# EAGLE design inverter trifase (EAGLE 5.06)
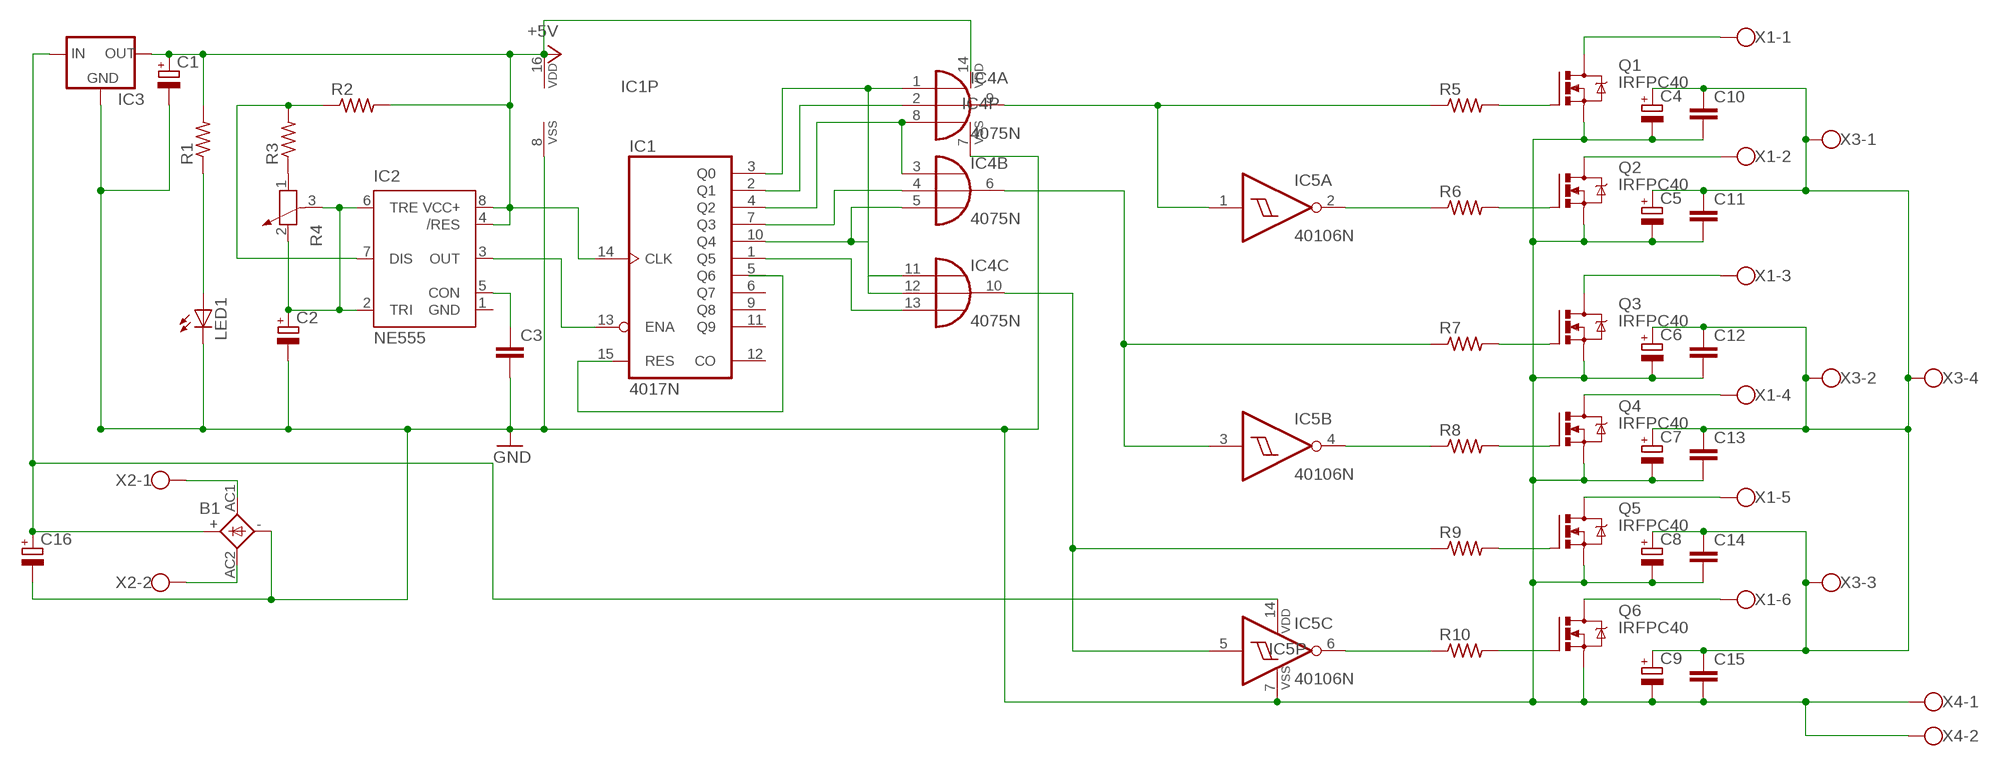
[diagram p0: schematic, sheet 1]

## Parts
B1  1KAB  [1KAB]
C1  CPOL-EUE2.5-7  [E2,5-7]
C2  CPOL-EUE2.5-7  [E2,5-7]
C3  C-EU050-025X075  [C050-025X075]
C4  CPOL-EUE10-25  [EB25D]
C5  CPOL-EUE10-25  [EB25D]
C6  CPOL-EUE10-25  [EB25D]
C7  CPOL-EUE10-25  [EB25D]
C8  CPOL-EUE10-25  [EB25D]
C9  CPOL-EUE10-25  [EB25D]
C10  C-EU050-025X075  [C050-025X075]
C11  C-EU050-025X075  [C050-025X075]
C12  C-EU050-025X075  [C050-025X075]
C13  C-EU050-025X075  [C050-025X075]
C14  C-EU050-025X075  [C050-025X075]
C15  C-EU050-025X075  [C050-025X075]
C16  CPOL-EUE2.5-7  [E2,5-7]
IC1  4017N  [DIL16]
IC2  NE555  [DIL-08]
IC3  78XXS  [78XXS]
IC4  4075N  [DIL14]
IC5  40106N  [DIL14]
LED1  LED3MM  [LED3MM]
Q1  IRFPC40  [TO247BV]
Q2  IRFPC40  [TO247BV]
Q3  IRFPC40  [TO247BV]
Q4  IRFPC40  [TO247BV]
Q5  IRFPC40  [TO247BV]
Q6  IRFPC40  [TO247BV]
R1  R-US_0207/10  [0207/10]
R2  R-US_0207/10  [0207/10]
R3  R-US_0207/10  [0207/10]
R4  POTENTIOMETER_PT-10S  [PT-10S]
R5  R-US_0207/10  [0207/10]
R6  R-US_0207/10  [0207/10]
R7  R-US_0207/10  [0207/10]
R8  R-US_0207/10  [0207/10]
R9  R-US_0207/10  [0207/10]
R10  R-US_0207/10  [0207/10]
X1  W237-6  [W237-6]
X2  W237-102  [W237-102]
X3  W237-4  [W237-4]
X4  W237-102  [W237-102]

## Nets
N$1: IC1.3(Q0) IC4.1(A:I0) IC4.12(C:I1)
N$2: IC1.2(Q1) IC4.2(A:I1)
N$3: IC1.4(Q2) IC4.3(B:I0) IC4.8(A:I2)
N$4: IC1.7(Q3) IC4.4(B:I1)
N$5: IC1.1(Q5) IC4.13(C:I2)
N$7: IC1.10(Q4) IC4.5(B:I2) IC4.11(C:I0)
N$8: IC4.9(A:O) IC5.1(A:I) R5.1
N$9: LED1.A R1.1
N$10: IC4.6(B:O) IC5.3(B:I) R7.1
N$11: IC2.6(TRE) R4.3
N$12: R3.1 R4.1
N$13: IC2.7(DIS) R2.1 R3.2
N$14: IC4.10(C:O) IC5.5(C:I) R9.1
N$15: C2.+ IC2.2(TRI) R4.2
N$16: IC5.2(A:O) R6.1
N$17: IC5.4(B:O) R8.1
N$18: IC5.6(C:O) R10.1
N$19: C3.1 IC2.5(CON)
N$20: Q1.G R5.2
N$21: Q2.G R6.2
N$22: Q3.G R7.2
N$23: Q4.G R8.2
N$24: Q5.G R9.2
N$25: Q6.G R10.2
N$31: Q1.D X1.1
N$32: Q2.D X1.2
N$33: C16.+ IC3.IN IC5.14(P:VDD)
N$34: Q3.D X1.3
N$35: Q4.D X1.4
N$36: Q5.D X1.5
N$37: Q6.D X1.6
N$39: B1.AC1 X2.1
N$40: B1.AC2 X2.2
N$41: IC1.13(ENA) IC2.3(OUT)
N$43: C4.+ C5.+ C6.+ C7.+ C8.+ C9.+ C10.1 C11.1 C12.1 C13.1 C14.1 C15.1 X3.1 X3.2 X3.3 X3.4
VDD: C1.+ IC1.14(CLK) IC1.16(VDD) IC2.4(/RES) IC2.8(VCC+) IC3.OUT R1.2 R2.2 ; supply symbol labelled +5V
VSS: B1.- C1.- C2.- C3.2 C4.- C5.- C6.- C7.- C8.- C9.- C10.2 C11.2 C12.2 C13.2 C14.2 C15.2 C16.- IC1.8(VSS) IC3.GND IC4.7(P:VSS) IC5.7(P:VSS) LED1.K(C) Q1.S Q2.S Q3.S Q4.S Q5.S Q6.S X4.1 X4.2 ; supply symbol labelled GND
Unconnected: B1.+ IC1.5(Q6) IC1.6(Q7) IC1.9(Q8) IC1.11(Q9) IC1.12(CO) IC1.15(RES) IC5.8(D:O) IC5.9(D:I) IC5.10(E:O) IC5.11(E:I) IC5.12(F:O) IC5.13(F:I)

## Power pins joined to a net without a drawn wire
VDD: IC4.14(P:VDD)
VSS: IC2.1(GND)

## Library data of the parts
B1 = rectifier:1KAB: RECTIFIER grid 5,08 x 5,08 mm
C1 C2 C4-C9 C16 = resistor:CPOL-EU: POLARIZED CAPACITOR, European symbol
C3 C10-C15 = resistor:C-EU: CAPACITOR, European symbol
IC1 = 40xx:4017: COUNTER/DIVIDER
IC2 = st-microelectronics:NE555: General purpose bipolar Timer
IC3 = v-reg:78XXS: VOLTAGE REGULATOR
IC4 = 40xx:4075: Triple 3-input OR
IC5 = 40xx:40106: Hex SCHMITT TRIGGER
LED1 = led:LED: LED
Q1-Q6 = transistor-power:IRFPC40: N-CHANNEL MOS FET
R1-R3 R5-R10 = resistor:R-US_: RESISTOR, American symbol
R4 = rcl:POTENTIOMETER_: Potentiometer
X1 = con-wago-500:W237-6: WAGO SCREW CLAMP
X2 X4 = con-wago-500:W237-102: WAGO SCREW CLAMP
X3 = con-wago-500:W237-4: WAGO SCREW CLAMP

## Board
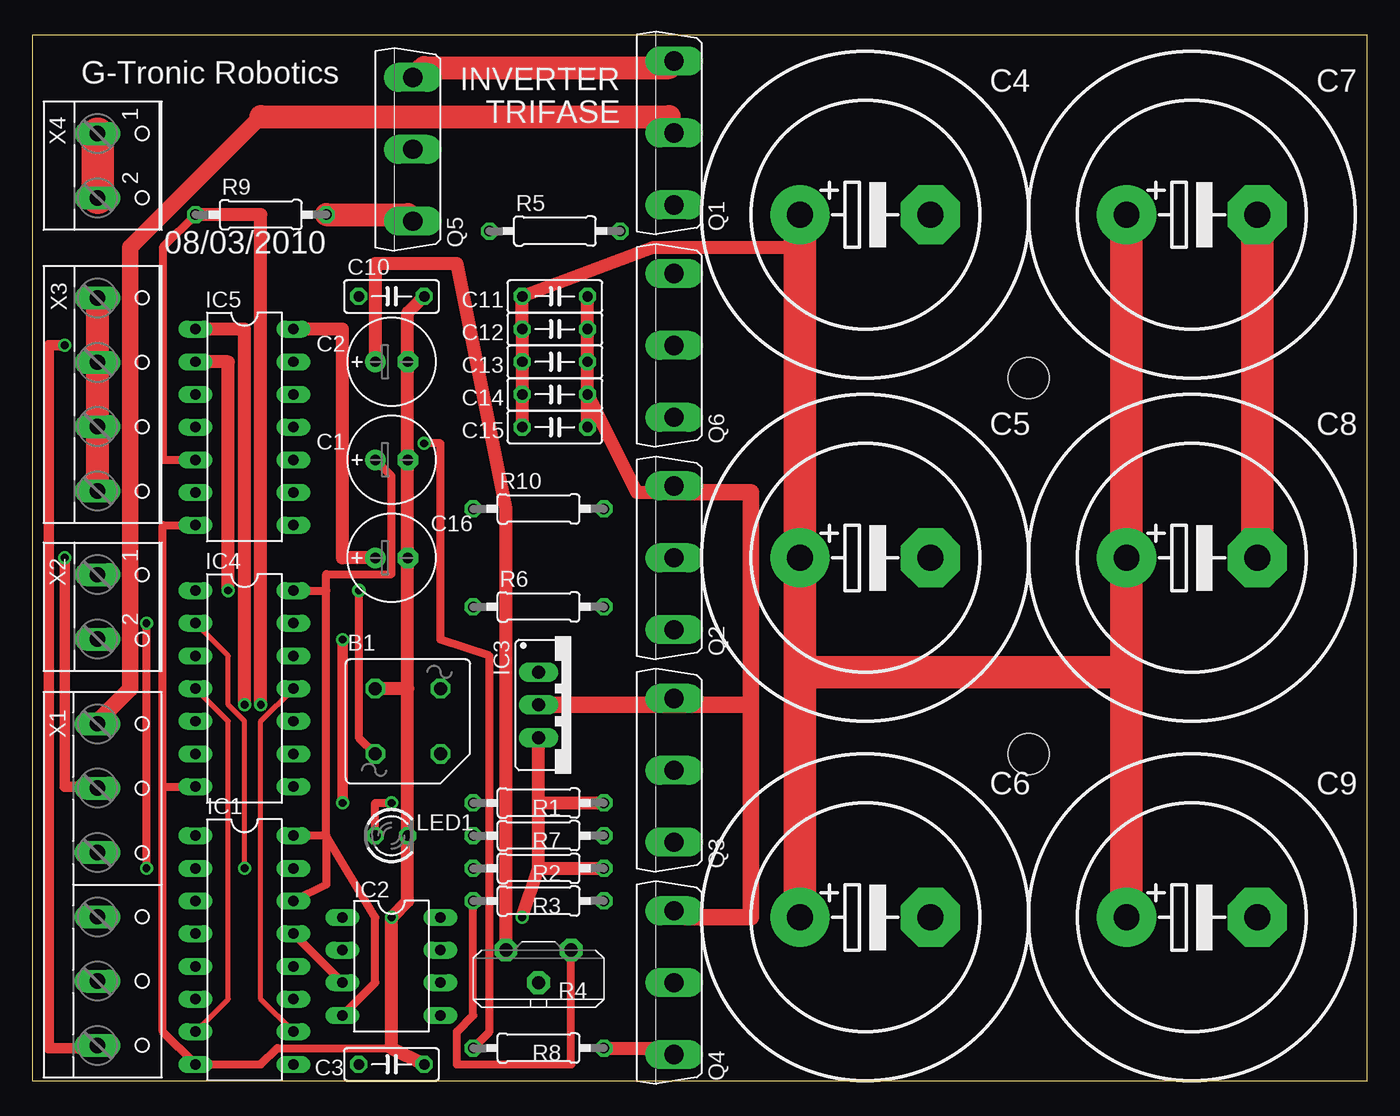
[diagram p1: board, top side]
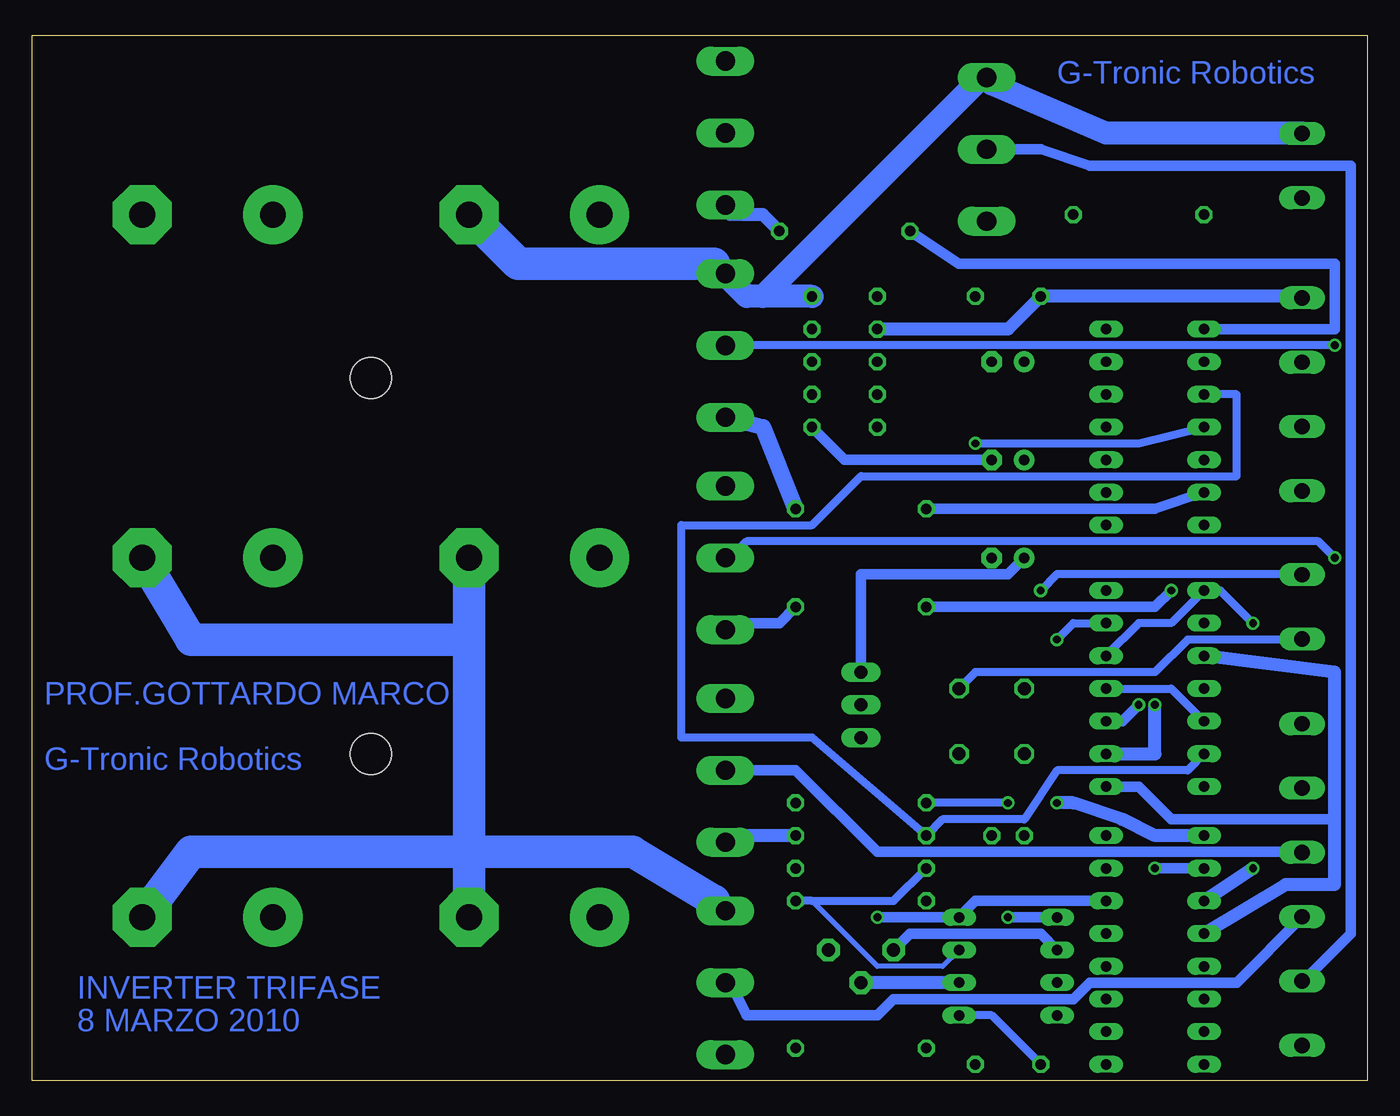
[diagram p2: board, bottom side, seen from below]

Size 103.81 x 81.27 mm. Coordinates in mm from the lower left corner, seen from the top.
Outline: 0,0 103.81,0 103.81,81.27 0,81.27 0,0
Copper layers (1*16): Top 0.035mm / dielectric 1.5mm / Bottom 0.035mm
Design rules "default": minimum track width 10mil, minimum drill 24mil, track to track 8mil, track to pad 8mil, pad to pad 8mil, via to via 8mil, smd to smd 8mil, copper to edge 40mil, drill to drill 8mil, minimum pad ring 10mil, minimum via ring 8mil, stop-mask expansion 4mil, vias tented up to drill 0mil, thermal gap 10mil
Holes 3.2 mm at 77.47,54.61 77.47,25.4

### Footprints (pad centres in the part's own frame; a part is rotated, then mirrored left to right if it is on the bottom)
1KAB = drill 1.016 octagon: + 2.54,-2.54; - -2.54,2.54; AC1 -2.54,-2.54; AC2 2.54,2.54
E2,5-7 = drill 0.813 pad 1.6 round: + -1.27,0 | drill 0.813 pad 1.6 octagon: - 1.27,0
C050-025X075 = drill 0.813 octagon: 1 -2.54,0; 2 2.54,0
EB25D = drill 2.007 pad 4.597 round: + -5.08,0 | drill 2.007 pad 4.597 octagon: - 5.08,0
DIL16 = drill 0.813 long: 1 -8.89,-3.81; 2 -6.35,-3.81; 3 -3.81,-3.81; 4 -1.27,-3.81; 5 1.27,-3.81; 6 3.81,-3.81; 7 6.35,-3.81; 8 8.89,-3.81; 9 8.89,3.81; 10 6.35,3.81; 11 3.81,3.81; 12 1.27,3.81; 13 -1.27,3.81; 14 -3.81,3.81; 15 -6.35,3.81; 16 -8.89,3.81
DIL-08 = drill 0.813 long: 1 -3.81,-3.81; 2 -1.27,-3.81; 3 1.27,-3.81; 4 3.81,-3.81; 5 3.81,3.81; 6 1.27,3.81; 7 -1.27,3.81; 8 -3.81,3.81
78XXS = drill 1.016 long: GND 0,-2.54; IN -2.54,-2.54; OUT 2.54,-2.54
DIL14 = drill 0.813 long: 1 -7.62,-3.81; 2 -5.08,-3.81; 3 -2.54,-3.81; 4 0,-3.81; 5 2.54,-3.81; 6 5.08,-3.81; 7 7.62,-3.81; 8 7.62,3.81; 9 5.08,3.81; 10 2.54,3.81; 11 0,3.81; 12 -2.54,3.81; 13 -5.08,3.81; 14 -7.62,3.81
LED3MM = drill 0.813 octagon: A -1.27,0; K 1.27,0
TO247BV = drill 1.499 long: D 0,-2.921; G -5.588,-2.921; S 5.588,-2.921
0207/10 = drill 0.813 octagon: 1 -5.08,0; 2 5.08,0
PT-10S = drill 1.016 pad 1.778 octagon: 1 -2.54,-1.27; 2 2.54,-1.27; 3 0,1.27
W237-6 = drill 1.194 long: 1 -12.5,-1.27; 2 -7.5,-1.27; 3 -2.5,-1.27; 4 2.5,-1.27; 5 7.5,-1.27; 6 12.5,-1.27
W237-102 = drill 1.194 long: 1 -2.5,-1.27; 2 2.5,-1.27
W237-4 = drill 1.194 long: 1 -7.5,-1.27; 2 -2.5,-1.27; 3 2.5,-1.27; 4 7.5,-1.27

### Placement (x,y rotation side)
B1  29.21,27.94 0 top
C1  27.94,48.26 0 top
C2  27.94,55.88 0 top
C3  27.94,1.27 0 top
C4  64.77,67.31 0 top
C5  64.77,40.64 0 top
C6  64.77,12.7 0 top
C7  90.17,67.31 0 top
C8  90.17,40.64 0 top
C9  90.17,12.7 0 top
C10  27.94,60.96 0 top
C11  40.64,60.96 0 top
C12  40.64,58.42 0 top
C13  40.64,55.88 0 top
C14  40.64,53.34 0 top
C15  40.64,50.8 0 top
C16  27.94,40.64 0 top
IC1  16.51,10.16 270 top
IC2  27.94,8.89 270 top
IC3  41.91,29.21 270 top
IC4  16.51,30.48 270 top
IC5  16.51,50.8 270 top
LED1  27.94,19.05 0 top
Q1  46.99,73.66 90 top
Q2  46.99,40.64 90 top
Q3  46.99,24.13 90 top
Q4  46.99,7.62 90 top
Q5  26.67,72.39 90 top
Q6  46.99,57.15 90 top
R1  39.37,21.59 0 top
R2  39.37,16.51 0 top
R3  39.37,13.97 0 top
R4  39.37,8.89 180 top
R5  40.64,66.04 0 top
R6  39.37,36.83 0 top
R7  39.37,19.05 0 top
R8  39.37,2.54 0 top
R9  17.78,67.31 0 top
R10  39.37,44.45 0 top
X1  6.35,15.24 270 top
X2  6.35,36.83 270 top
X3  6.35,53.34 270 top
X4  6.35,71.12 270 top

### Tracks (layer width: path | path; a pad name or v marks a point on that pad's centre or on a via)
N$1  (via drill 0.61)
  Top 0.61: v8.89,16.51 v8.89,35.56
  Bottom 0.61: v8.89,35.56 11.43,38.1 IC4.1 15.24,35.56 17.78,35.56 IC4.12
  Bottom 1.016: IC1.3 v8.89,16.51
N$2  (via drill 0.61)
  Top 0.406: v16.51,16.51 16.51,27.94 15.24,29.21 15.24,33.02 IC4.2
  Bottom 0.813: IC1.2 v16.51,16.51
N$3
  Bottom 0.813: IC4.8 17.78,22.86 15.24,20.32 2.54,20.32
  Bottom 1.016: IC1.4 6.35,15.24 2.54,15.24 2.54,20.32 2.54,31.75 IC4.3
N$4
  Top 0.406: IC1.7 15.24,6.35 15.24,27.94 IC4.4
N$5  (via drill 0.61)
  Top 0.813: v24.13,21.59 v24.13,34.29
  Bottom 0.61: v24.13,34.29 22.86,35.56 IC4.13
  Bottom 1.016: IC1.1 16.51,19.05 19.05,20.32 22.86,21.59 v24.13,21.59
N$7
  Top 0.406: IC1.10 17.78,6.35 17.78,27.94 IC4.11
  Bottom 0.61: IC4.5 15.24,30.48 IC4.11
N$8  (via drill 0.61)
  Top 1.016: v16.51,29.21 16.51,58.42 IC5.1
  Bottom 0.813: R5.1 31.75,63.5 2.54,63.5 2.54,58.42 IC5.1
  Bottom 1.016: IC4.9 16.51,25.4 v16.51,29.21
N$9  (via drill 0.61)
  Top 0.61: LED1.A 26.67,21.59 v27.94,21.59
  Bottom 0.61: v27.94,21.59 R1.1
N$10
  Bottom 0.61: IC4.6 13.97,24.13 24.13,24.13 26.67,20.32 33.02,20.32 R7.1 43.18,26.67 53.34,26.67 53.34,43.18 43.18,43.18 39.37,46.99 10.16,46.99 10.16,53.34 IC5.3
N$11
  Bottom 1.016: IC2.6 R4.3
N$12
  Top 0.61: R3.1 34.29,5.08 33.02,3.81 33.02,1.27 41.91,1.27 R4.1
N$13
  Bottom 0.406: IC2.7 33.02,8.89 38.1,8.89 43.18,13.97
  Bottom 0.61: R3.2 43.18,13.97 36.83,13.97 R2.1
N$14  (via drill 0.61)
  Top 0.61: IC5.5 10.16,48.26 10.16,64.77 R9.1
  Top 1.016: v17.78,29.21 17.78,67.31 R9.1
  Bottom 0.813: IC4.10 19.05,27.94 v17.78,29.21
N$15
  Top 1.016: C2.+ 26.67,63.5 33.02,63.5 36.83,44.45 R4.2
  Bottom 0.813: IC2.2 25.4,11.43 35.56,11.43 R4.2
N$16  (via drill 0.61)
  Top 1.016: IC5.2 15.24,55.88 v15.24,38.1
  Bottom 0.813: v15.24,38.1 16.51,36.83 R6.1
N$17  (via drill 0.61)
  Top 0.61: R8.1 35.56,3.81 35.56,33.02 31.75,34.29 31.75,49.53 v30.48,49.53
  Bottom 0.61: v30.48,49.53 17.78,49.53 IC5.4
N$18
  Bottom 0.813: IC5.6 16.51,44.45 R10.1
N$19
  Bottom 0.61: C3.1 29.21,5.08 IC2.5
N$20
  Bottom 1.016: R5.2 46.99,67.31 49.53,67.31 Q1.G
N$21
  Bottom 0.813: R6.2 45.72,35.56 49.53,35.56 Q2.G
N$22
  Bottom 1.016: R7.2 49.53,19.05 Q3.G
N$23
  Top 1.016: R8.2 49.53,2.54 Q4.G
N$24
  Top 0.254: 29.21,67.31 Q5.G
  Top 1.778: R9.2 29.21,67.31
N$25
  Bottom 1.27: R10.2 46.99,50.8 Q6.G
N$31
  Top 0.254: X1.1 5.08,27.94 | 49.53,73.66 Q1.D
  Top 1.27: 5.08,27.94 7.62,30.48 7.62,64.77 17.78,74.93
  Top 1.778: 17.78,74.93 49.53,74.93 49.53,73.66
N$32  (via drill 0.61)
  Top 0.254: X1.2 5.08,22.86
  Top 0.813: 5.08,22.86 2.54,22.86 v2.54,40.64
  Bottom 0.254: 49.53,40.64 Q2.D
  Bottom 0.61: v2.54,40.64 3.81,41.91 48.26,41.91 49.53,40.64
N$33
  Top 1.016: IC5.14 24.13,58.42 24.13,40.64 C16.+
  Bottom 0.813: IC3.IN 39.37,39.37 27.94,39.37 C16.+
N$34
  Bottom 0.254: X1.3 5.08,17.78
  Bottom 0.813: 5.08,17.78 38.1,17.78 44.45,24.13 Q3.D
N$35
  Bottom 0.254: X1.4 5.08,12.7 | 49.53,7.62 Q4.D
  Bottom 0.813: 5.08,12.7 10.16,7.62 21.59,7.62 22.86,6.35 36.83,6.35 38.1,5.08 48.26,5.08 49.53,7.62
N$36
  Bottom 0.254: X1.5 5.08,7.62
  Bottom 0.813: 5.08,7.62 1.27,11.43 1.27,71.12 21.59,71.12 25.4,72.39 Q5.D
N$37  (via drill 0.61)
  Top 0.254: X1.6 5.08,2.54
  Top 0.813: 5.08,2.54 1.27,2.54 1.27,57.15 v2.54,57.15
  Bottom 0.61: v2.54,57.15 Q6.D
N$39  (via drill 0.61)
  Top 0.61: B1.AC1 25.4,26.67 v25.4,38.1
  Bottom 0.254: X2.1 5.08,39.37
  Bottom 0.61: v25.4,38.1 24.13,39.37 5.08,39.37
N$40
  Bottom 0.254: X2.2 5.08,34.29
  Bottom 0.61: B1.AC2 30.48,31.75 16.51,31.75 13.97,34.29 5.08,34.29
N$41
  Top 0.61: IC1.13 IC2.3
N$43
  Top 0.254: X3.4 5.08,45.72 | X3.1 5.08,60.96
  Top 1.016: C15.1 C14.1 C13.1 C12.1 C11.1 48.26,64.77 59.69,64.77
  Top 1.778: X3.4 X3.3 X3.2 X3.1
  Top 2.54: 85.09,31.75 C8.+ C7.+ | 85.09,31.75 C9.+ | 59.69,31.75 C5.+ 59.69,64.77 C4.+ | 59.69,31.75 C6.+ | 59.69,31.75 85.09,31.75
  Bottom 0.254: X3.1 5.08,60.96
  Bottom 1.016: C12.1 27.94,58.42 C10.1 5.08,60.96
VDD  (via drill 0.61)
  Top 0.61: 22.86,19.05 26.67,12.7 26.67,7.62 IC2.4 | 22.86,19.05 IC1.16 | 22.86,19.05 22.86,38.1 | C1.+ 27.94,46.99 27.94,39.37 22.86,39.37 22.86,38.1 | IC4.14 22.86,38.1 | 22.86,19.05 22.86,15.24 IC1.14
  Top 1.016: 39.37,16.51 39.37,21.59 | 39.37,16.51 R2.2 | 39.37,21.59 IC3.OUT | 39.37,21.59 R1.2 | v38.1,12.7 39.37,16.51
  Bottom 0.813: IC1.14 30.48,13.97 IC2.8 v38.1,12.7
VSS  (via drill 0.61)
  Top 0.254: X4.2 5.08,68.58 | X4.1 5.08,73.66 | 49.53,78.74 Q1.S
  Top 0.61: 10.16,22.86 10.16,3.81 IC1.8 17.78,1.27 19.05,2.54 27.94,2.54 | 10.16,22.86 IC4.7 | IC5.7 10.16,43.18 10.16,22.86
  Top 1.016: 50.8,12.7 Q4.S | C15.2 C14.2 | C11.2 C12.2 C13.2 C14.2 | C14.2 46.99,45.72 49.53,45.72 Q2.S | C3.2 27.94,2.54 v27.94,12.7 29.21,13.97 LED1.K 29.21,30.48 | 29.21,30.48 B1.- | 29.21,30.48 C16.- C1.- C2.- 29.21,59.69 C10.2 | 49.53,29.21 Q3.S
  Top 1.27: 50.8,12.7 55.88,12.7 55.88,29.21 | 49.53,45.72 55.88,45.72 55.88,29.21 | 55.88,29.21 IC3.GND
  Top 1.778: 49.53,78.74 30.48,78.74 Q5.S
  Top 2.54: C8.- C7.- | X4.1 X4.2
  Bottom 0.254: Q4.S 50.8,13.97 | 5.08,73.66 X4.1 | 49.53,62.23 Q6.S 50.8,63.5 | 30.48,77.47 Q5.S
  Bottom 0.813: v27.94,12.7 IC2.1 | C15.2 40.64,48.26 C1.-
  Bottom 1.778: 5.08,73.66 20.32,73.66 29.21,77.47 Q5.S | 49.53,62.23 48.26,60.96 46.99,60.96 | C11.2 46.99,60.96 | 46.99,60.96 30.48,77.47
  Bottom 2.54: 69.85,34.29 C5.- | 69.85,17.78 69.85,34.29 | 69.85,17.78 C6.- | C9.- 91.44,17.78 69.85,17.78 | 50.8,13.97 57.15,17.78 69.85,17.78 | C8.- 91.44,34.29 69.85,34.29 | C4.- 66.04,63.5 50.8,63.5

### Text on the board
Bottom: G-Tronic Robotics | PROF.GOTTARDO MARCO | G-Tronic Robotics | INVERTER TRIFASE | 8 MARZO 2010
tNames: INVERTER | G-Tronic Robotics | TRIFASE | 08/03/2010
